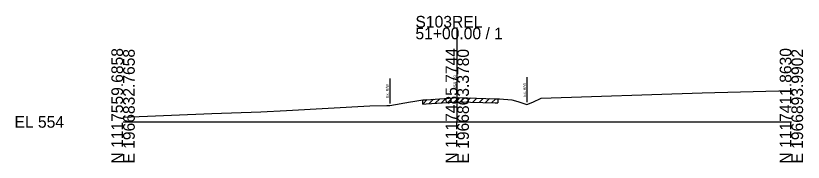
# Model space of a CAD drawing. Extents: x -26 to 163, y -10 to 24518.
# Drawn here: x -25.7 to 162.8, y 1490.3 to 1525.5 of the extents above; entities that cross this region are included whole.
import ezdxf

# ---------------------------------------------------------------- set-up
doc = ezdxf.new("R2010")
doc.units = 0
for name, color, linetype in [('RD_GPK_XS_Cell', 7, 'Continuous'), ('RD_XS_ExGround', 7, 'Continuous'), ('RD_XS_ExPaveRet', 7, 'Continuous'), ('RD_XS_ExRW', 7, 'Continuous'), ('RD_XS_TX_Elev_EX', 7, 'Continuous')]:
    doc.layers.add(name, color=color, linetype=linetype)

msp = doc.modelspace()

# ---------------------------------------------------------------- linework, layer by layer
at = {"layer": 'RD_GPK_XS_Cell'}
for p, q in [((80, 1500), (80, 1522.61)), ((0, 1500), (80, 1500)), ((80, 1500), (160, 1500))]:
    msp.add_line(p, q, dxfattribs=at)
at = {"layer": 'RD_XS_ExGround'}
msp.add_lwpolyline([(0, 1501.09), (21.24, 1502), (32.96, 1502.38), (39.12, 1502.72), (59.1, 1503.85), (63.15, 1503.9), (63.83, 1503.91), (68.81, 1504.78), (69.4, 1504.87), (71.74, 1505.26), (72.56, 1505.31), (80.25, 1505.81), (89.05, 1505.56), (89.73, 1505.54), (90.12, 1505.51), (93.07, 1505.32), (94.54, 1504.92), (96.69, 1504.19), (98.11, 1504.75), (100.08, 1505.71), (138.67, 1506.93), (160, 1507.54)], dxfattribs=at)
at = {"layer": 'RD_XS_ExPaveRet'}
for p, q in [((71.74, 1504.26), (72.81, 1505.33)), ((71.74, 1504.26), (71.74, 1505.26)), ((72.56, 1504.31), (80.25, 1504.81)), ((73.24, 1504.36), (74.31, 1505.43)), ((74.74, 1504.45), (75.81, 1505.52)), ((76.24, 1504.55), (77.31, 1505.62)), ((77.74, 1504.65), (78.81, 1505.72)), ((79.24, 1504.75), (80.31, 1505.81)), ((80.25, 1504.81), (89.05, 1504.56)), ((80.74, 1504.8), (81.71, 1505.77)), ((82.24, 1504.75), (83.21, 1505.73)), ((83.74, 1504.71), (84.71, 1505.68)), ((85.24, 1504.67), (86.21, 1505.64)), ((86.74, 1504.62), (87.71, 1505.6)), ((88.24, 1504.58), (89.21, 1505.55)), ((89.05, 1504.56), (89.73, 1504.54)), ((89.73, 1505.54), (89.73, 1504.54)), ((71.74, 1504.26), (72.56, 1504.31))]:
    msp.add_line(p, q, dxfattribs=at)
at = {"layer": 'RD_XS_ExRW'}
for p, q in [((63.83, 1510.41), (63.83, 1504.41)), ((96.69, 1510.7), (96.69, 1504.7)), ((96.69, 1510.69), (96.69, 1504.69))]:
    msp.add_line(p, q, dxfattribs=at)

# ---------------------------------------------------------------- texts
at = {"layer": 'RD_GPK_XS_Cell'}
for s, p in [('S103REL', (70, 1522.61)), ('51+00.00 / 1', (70, 1519.81)), ('EL 554', (-26, 1498.6))]:
    msp.add_text(s, height=2.8, dxfattribs=at).set_placement(p)
for s, p in [('N 1117559.6858', (0, 1490)), ('E 1966832.7658', (2.8, 1490)), ('N 1117485.7744', (80, 1490)), ('E 1966863.3780', (82.8, 1490)), ('N 1117411.8630', (160, 1490)), ('E 1966893.9902', (162.8, 1490))]:
    msp.add_text(s, height=2.8, rotation=90, dxfattribs=at).set_placement(p)
at = {"layer": 'RD_XS_ExRW'}
for p in [(63.58, 1505.76), (96.44, 1506.04), (96.44, 1506.04)]:
    msp.add_text('Ex. R/W ', height=0.65, rotation=90, dxfattribs=at).set_placement(p)
at = {"layer": 'RD_XS_TX_Elev_EX'}
msp.add_text('559.79', height=0.8, rotation=90, dxfattribs=at).set_placement((79.9, 1507.79))

doc.saveas('drawing.dxf')
